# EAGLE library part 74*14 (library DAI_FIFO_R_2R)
Hex INVERTER
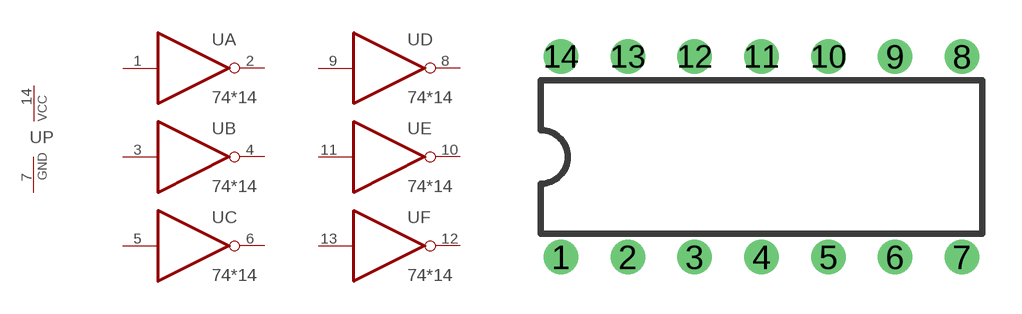
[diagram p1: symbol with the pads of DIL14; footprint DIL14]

Designator prefix U; gates A=7414 B=7414 C=7414 D=7414 E=7414 F=7414 P=PWRN

## 7414N, 74AC14N, 74ACT14N, 74ALS14N, 74AS14N, 74HC14N, 74HCT14N, 74LS14N, 74S14N  [DIL14]
1  A:I  in
2  A:O  out
3  B:I  in
4  B:O  out
5  C:I  in
6  C:O  out
7  P:GND  pwr
8  D:O  out
9  D:I  in
10  E:O  out
11  E:I  in
12  F:O  out
13  F:I  in
14  P:VCC  pwr

## Footprint DIL14 (pad centres in mm)
Dual In Line Package
drill 0.8 round: 1 -7.62,-3.81; 2 -5.08,-3.81; 3 -2.54,-3.81; 4 0,-3.81; 5 2.54,-3.81; 6 5.08,-3.81; 7 7.62,-3.81; 8 7.62,3.81; 9 5.08,3.81; 10 2.54,3.81; 11 0,3.81; 12 -2.54,3.81; 13 -5.08,3.81; 14 -7.62,3.81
